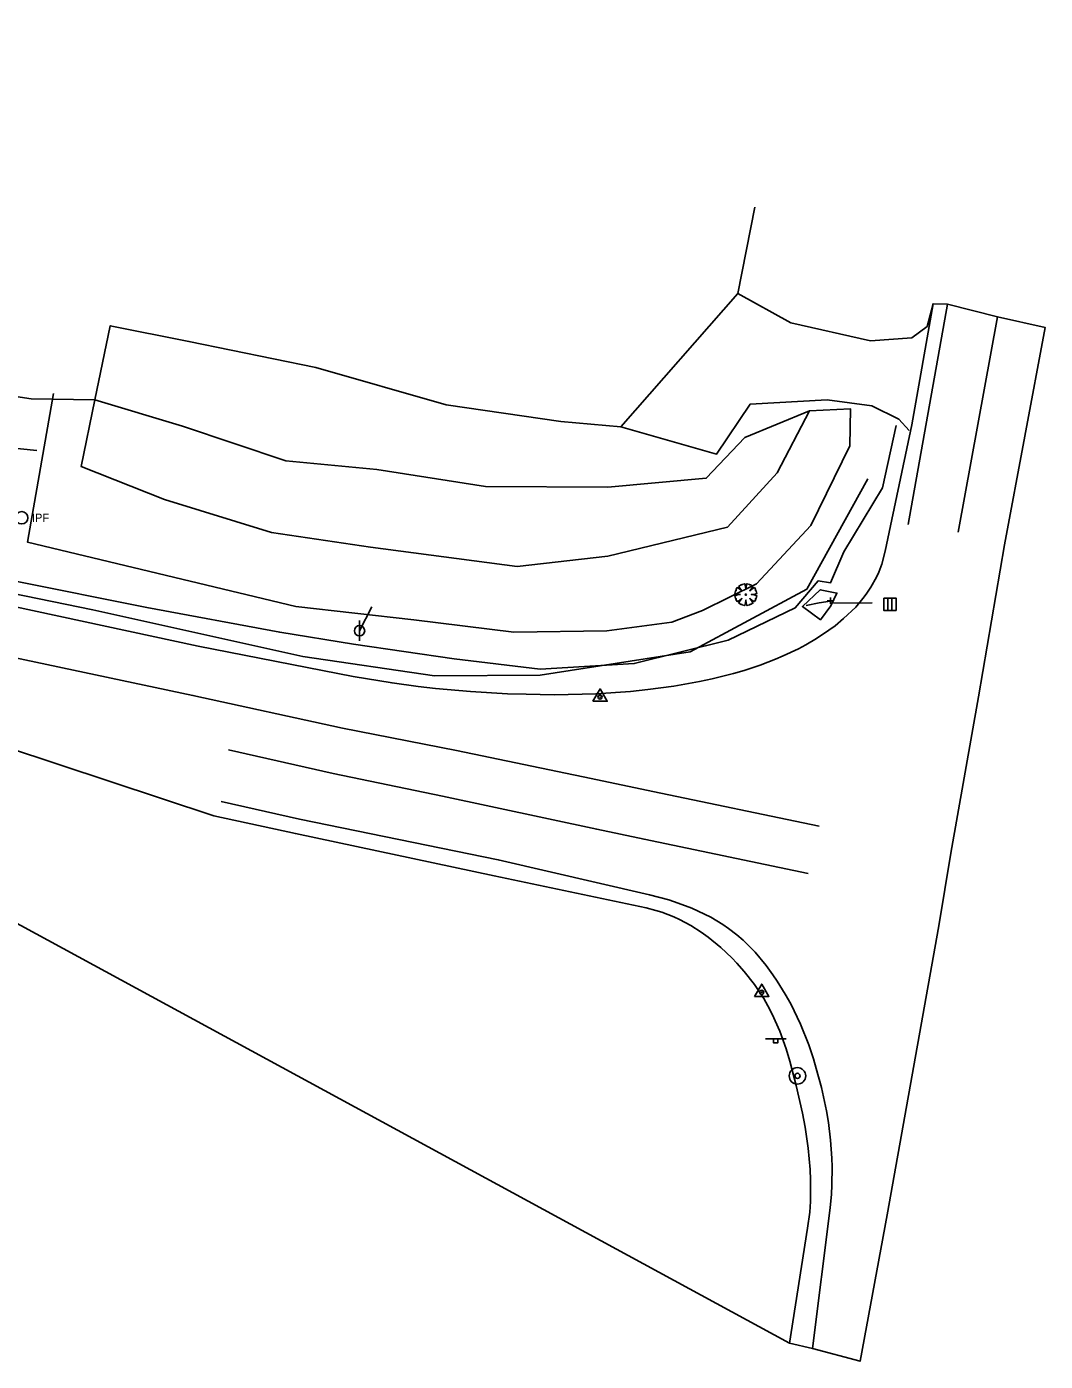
# Model space of a CAD drawing. Extents: x 1158469 to 1165378, y 609843 to 611748.
# Drawn here: x 1165130.6 to 1165377.8, y 609925.3 to 610249.2 of the extents above; entities that cross this region are included whole.
import ezdxf

# ---------------------------------------------------------------- set-up
doc = ezdxf.new("R2010")
doc.units = 0
for name, color, linetype in [('Exterior Boundary', 7, 'Continuous'), ('S_Control_Temp_Traverse', 7, 'Continuous'), ('S_Drainage_CB', 7, 'Continuous'), ('S_Drainage_Culvert_Top', 7, 'Continuous'), ('S_Drainage_Invert', 7, 'Continuous'), ('S_Drainage_RipRap', 7, 'Continuous'), ('S_Ground_Elevation', 7, 'Continuous'), ('S_Property_IronPipeFound', 7, 'Continuous'), ('S_Roadway_Centerline', 7, 'Continuous'), ('S_Roadway_Drive_Gravel', 7, 'Continuous'), ('S_Roadway_Edge_Pavement', 7, 'Continuous'), ('S_Roadway_Edge_TW', 7, 'Continuous'), ('S_Traffic_Sign_SinglePost', 7, 'Continuous'), ('S_Trees_Decid_NonPay', 7, 'Continuous'), ('S_Trees_HedgeLine', 7, 'Continuous'), ('S_Utilities_GuyWire3', 7, 'Continuous'), ('S_Utilities_Pole_Power', 7, 'Continuous'), ('S_Utilities_UG_Gas_Line', 7, 'Continuous'), ('S_Utilities_UG_Sanitary_MH', 7, 'Continuous')]:
    doc.layers.add(name, color=color, linetype=linetype)

msp = doc.modelspace()

# ---------------------------------------------------------------- linework, layer by layer
at = {"layer": 'Exterior Boundary'}
msp.add_lwpolyline([(1165125.5, 610033.08), (1165315.71, 609929.68), (1165321.34, 609928.43), (1165332.86, 609925.3), (1165339.45, 609960.81), (1165351.95, 610030.98), (1165354.88, 610048.57), (1165361.58, 610086.51), (1165367.96, 610123.43), (1165377.83, 610176.14), (1165366.26, 610178.75), (1165354.1, 610181.8), (1165350.58, 610181.93), (1165349.16, 610176.44), (1165345.45, 610173.65), (1165335.4, 610172.96), (1165316.03, 610177.29), (1165303.21, 610184.39), (1165274.79, 610152.06), (1165260.28, 610153.36), (1165232.4, 610157.43), (1165200.79, 610166.46), (1165170, 610172.78), (1165150.91, 610176.58), (1165147.13, 610158.61), (1165131.67, 610158.89), (1165111.05, 610162.04)], dxfattribs=at)
at = {"layer": 'S_Control_Temp_Traverse'}
for p, q in [((1165269.64, 610086.48), (1165269.89, 610086.48)), ((1165269.77, 610086.6), (1165269.77, 610086.35)), ((1165309, 610014.97), (1165309, 610014.72)), ((1165308.88, 610014.84), (1165309.13, 610014.84))]:
    msp.add_line(p, q, dxfattribs=at)
for points in [[(1165268.04, 610085.48), (1165271.5, 610085.48), (1165269.77, 610088.48)], [(1165307.27, 610013.84), (1165310.74, 610013.84), (1165309, 610016.84)]]:
    msp.add_lwpolyline(points, close=True, dxfattribs=at)
for centre in [(1165269.77, 610086.48), (1165309, 610014.84)]:
    msp.add_circle(centre, 0.5, dxfattribs=at)
at = {"layer": 'S_Drainage_CB'}
for p, q in [((1165339.6, 610110.52), (1165339.6, 610107.52)), ((1165340.6, 610110.52), (1165340.6, 610107.52))]:
    msp.add_line(p, q, dxfattribs=at)
msp.add_lwpolyline([(1165338.6, 610110.52), (1165341.6, 610110.52), (1165341.6, 610107.52), (1165338.6, 610107.52)], close=True, dxfattribs=at)
at = {"layer": 'S_Drainage_Culvert_Top'}
msp.add_lwpolyline([(1165326.39, 610109.26), (1165335.8, 610109.34)], dxfattribs=at)
at = {"layer": 'S_Drainage_Invert'}
for p, q in [((1165324.92, 610109.86), (1165326.42, 610109.86)), ((1165325.67, 610110.61), (1165325.67, 610109.11))]:
    msp.add_line(p, q, dxfattribs=at)
at = {"layer": 'S_Drainage_RipRap'}
msp.add_lwpolyline([(1165325.78, 610108.62), (1165323.24, 610105.26), (1165318.87, 610108.43), (1165323.22, 610112.52), (1165327.26, 610111.7)], close=True, dxfattribs=at)
at = {"layer": 'S_Ground_Elevation'}
for points in [[(1165131.67, 610158.89), (1165111.05, 610162.04), (1165081.66, 610169.51), (1165046.46, 610179.72), (1165010.53, 610187.31), (1164975.93, 610194.85), (1164954.17, 610199.11), (1164924.19, 610204.21), (1164911.82, 610196.02), (1164928.99, 610192.61), (1164954.02, 610185.41), (1164976.94, 610180.26), (1165003.93, 610175.22), (1165028.37, 610169.19), (1165050.08, 610165.24), (1165073.84, 610159.31), (1165096.89, 610152.98), (1165122.71, 610147.36), (1165133.09, 610146.34)], [(1165330.51, 610156.45), (1165320.59, 610155.91), (1165312.72, 610140.9), (1165300.67, 610127.75), (1165271.63, 610120.65), (1165249.68, 610118.14), (1165214.07, 610122.86), (1165190.07, 610126.42), (1165164.09, 610134.42), (1165143.88, 610142.41), (1165147.13, 610158.61), (1165150.91, 610176.58), (1165170, 610172.78), (1165200.79, 610166.46), (1165232.4, 610157.43), (1165260.28, 610153.36), (1165274.79, 610152.06)], [(1165130.83, 610124.06), (1165195.95, 610108.47), (1165224.59, 610105.19), (1165248.83, 610102.25), (1165271.38, 610102.55), (1165287.19, 610104.66), (1165294.61, 610107.47), (1165307.71, 610113.99), (1165320.93, 610128.15), (1165330.41, 610147.42), (1165330.51, 610156.45), (1165320.59, 610155.91), (1165304.87, 610149.46), (1165295.54, 610139.58), (1165271.68, 610137.46), (1165241.99, 610137.61), (1165215.59, 610141.67), (1165193.55, 610143.78), (1165168.4, 610152.23), (1165147.13, 610158.61)], [(1165341.63, 610152.38), (1165338.28, 610137.27), (1165328.96, 610121.76), (1165325.7, 610114.21), (1165322.7, 610114.67), (1165317.16, 610108.11), (1165300.9, 610100.28), (1165278.07, 610094.59), (1165255.25, 610093.27), (1165234.36, 610095.8), (1165209.94, 610099.32), (1165192.02, 610102.23), (1165159.8, 610108.25), (1165127.49, 610114.72)], [(1165325.61, 610109.73), (1165322.96, 610109.38), (1165319.8, 610108.74)]]:
    msp.add_lwpolyline(points, dxfattribs=at)
at = {"layer": 'S_Property_IronPipeFound'}
msp.add_circle((1165129.41, 610130), 1.5, dxfattribs=at)
at = {"layer": 'S_Roadway_Centerline'}
for points in [[(1165322.92, 610055.12), (1165282.59, 610063.58), (1165267.59, 610066.74), (1165234.97, 610073.48), (1165207.29, 610078.95), (1165170.95, 610086.9), (1165118.3, 610098.03), (1165065.91, 610108.93), (1165025.19, 610117.35), (1164995.59, 610123.89), (1164956.04, 610131.83), (1164919.32, 610140.12), (1164874.11, 610149.34), (1164822.77, 610160.96), (1164779.77, 610169.22), (1164696.7, 610187.78), (1164657.25, 610196.14), (1164616.44, 610205.3), (1164588.01, 610211.13), (1164540.84, 610220.89), (1164515.97, 610226.08), (1164470.96, 610235.38), (1164428.02, 610243.9), (1164400.81, 610249.16)], [(1165377.83, 610176.14), (1165367.96, 610123.43), (1165361.58, 610086.51), (1165354.88, 610048.57)], [(1165332.86, 609925.3), (1165339.45, 609960.81), (1165351.95, 610030.98)]]:
    msp.add_lwpolyline(points, dxfattribs=at)
at = {"layer": 'S_Roadway_Drive_Gravel'}
for points in [[(1165349.16, 610176.44), (1165345.45, 610173.65), (1165335.4, 610172.96), (1165316.03, 610177.29), (1165303.21, 610184.39), (1165307.34, 610205.39)], [(1165274.79, 610152.06), (1165297.99, 610145.41), (1165306.18, 610157.53), (1165324.85, 610158.65), (1165335.71, 610157.12), (1165342.28, 610153.92), (1165344.82, 610151.15)]]:
    msp.add_lwpolyline(points, dxfattribs=at)
at = {"layer": 'S_Roadway_Edge_Pavement'}
for points in [[(1165350.58, 610181.93), (1165345.47, 610152.58), (1165340.28, 610128.03), (1165339, 610121.88), (1165338.16, 610118.76), (1165337.41, 610116.8), (1165336.83, 610115.55), (1165335.51, 610113.16), (1165334.38, 610111.47), (1165333.57, 610110.39), (1165331.81, 610108.33), (1165328.89, 610105.51), (1165326.79, 610103.79), (1165325.33, 610102.71), (1165322.32, 610100.71), (1165319.68, 610099.17), (1165317.89, 610098.21), (1165314.23, 610096.46), (1165312.38, 610095.67), (1165308.6, 610094.23), (1165304.77, 610092.97), (1165302.19, 610092.22), (1165296.96, 610090.92), (1165293.87, 610090.25), (1165287.65, 610089.15), (1165281.39, 610088.3), (1165277.19, 610087.87), (1165268.78, 610087.3), (1165265.4, 610087.17), (1165258.62, 610087.06), (1165251.84, 610087.15), (1165247.33, 610087.3), (1165238.31, 610087.83), (1165229.85, 610088.58), (1165225.63, 610089.05), (1165219.3, 610089.9), (1165209.85, 610091.51), (1165172.21, 610098.85), (1165121.41, 610109.77)], [(1165315.71, 609929.68), (1165320.15, 609957.57), (1165320.64, 609961.5), (1165320.82, 609964.11), (1165320.88, 609969.3), (1165320.77, 609971.88), (1165320.3, 609977.01), (1165319.54, 609982.11), (1165318.9, 609985.5), (1165317.38, 609992.24), (1165315.81, 609998.16), (1165314.92, 610001.09), (1165313.38, 610005.39), (1165311.54, 610009.56), (1165310.5, 610011.58), (1165309.49, 610013.33), (1165307.26, 610016.7), (1165304.77, 610019.9), (1165302.98, 610021.92), (1165301.73, 610023.22), (1165299.11, 610025.69), (1165295.98, 610028.26), (1165294.34, 610029.45), (1165291.78, 610031.08), (1165289.09, 610032.52), (1165287.7, 610033.16), (1165284.8, 610034.27), (1165283.3, 610034.73), (1165280.97, 610035.31), (1165244.04, 610043.12), (1165195.85, 610053.35), (1165176.01, 610057.63), (1165125.74, 610074.35)]]:
    msp.add_lwpolyline(points, dxfattribs=at)
at = {"layer": 'S_Roadway_Edge_TW'}
for points in [[(1165354.1, 610181.8), (1165344.55, 610128.37)], [(1165366.26, 610178.75), (1165356.7, 610126.46)], [(1165320.28, 610043.71), (1165280.46, 610051.98), (1165268.97, 610054.42), (1165231.54, 610062.41), (1165205.02, 610067.95), (1165179.6, 610073.67)], [(1165321.34, 609928.43), (1165325.58, 609962.51), (1165325.92, 609965.85), (1165326.05, 609968.06), (1165326.11, 609972.45), (1165326.04, 609974.63), (1165325.72, 609978.96), (1165325.17, 609983.26), (1165324.69, 609986.1), (1165323.48, 609991.75), (1165322.25, 609996.38), (1165321.56, 609998.68), (1165320.4, 610002.09), (1165318.4, 610007.12), (1165316.05, 610012.02), (1165314.73, 610014.4), (1165312.78, 610017.58), (1165311.73, 610019.12), (1165310.07, 610021.37), (1165307.39, 610024.56), (1165304.48, 610027.47), (1165302.94, 610028.8), (1165300.93, 610030.35), (1165299.54, 610031.31), (1165296.65, 610033.05), (1165295.14, 610033.84), (1165292.02, 610035.27), (1165288.74, 610036.51), (1165286.48, 610037.25), (1165281.74, 610038.5), (1165245.05, 610047), (1165196.87, 610056.84), (1165177.78, 610061.12)]]:
    msp.add_lwpolyline(points, dxfattribs=at)
at = {"layer": 'S_Traffic_Sign_SinglePost'}
msp.add_line((1165309.9, 610003.55), (1165314.9, 610003.55), dxfattribs=at)
msp.add_lwpolyline([(1165311.9, 610003.55), (1165312.9, 610003.55), (1165312.9, 610002.55), (1165311.9, 610002.55)], close=True, dxfattribs=at)
at = {"layer": 'S_Trees_Decid_NonPay'}
msp.add_lwpolyline([(1165303.82, 610111.34), (1165303.13, 610111.39), (1165302.5, 610111.6), (1165302.65, 610112.29), (1165302.81, 610112.29), (1165302.76, 610112.51), (1165303.08, 610113.04), (1165303.61, 610112.77), (1165304.2, 610112.29), (1165303.72, 610112.88), (1165303.45, 610113.41), (1165303.98, 610113.73), (1165304.2, 610113.68), (1165304.2, 610113.84), (1165304.89, 610113.99), (1165305.1, 610113.36), (1165305.15, 610112.67), (1165305.21, 610113.36), (1165305.42, 610113.99), (1165306.11, 610113.84), (1165306.11, 610113.68), (1165306.32, 610113.73), (1165306.85, 610113.41), (1165306.59, 610112.88), (1165306.11, 610112.29), (1165306.69, 610112.77), (1165307.23, 610113.04), (1165307.54, 610112.51), (1165307.49, 610112.29), (1165307.65, 610112.29), (1165307.81, 610111.6), (1165307.17, 610111.39), (1165306.48, 610111.34), (1165307.17, 610111.28), (1165307.81, 610111.07), (1165307.65, 610110.38), (1165307.49, 610110.38), (1165307.54, 610110.17), (1165307.23, 610109.64), (1165306.69, 610109.9), (1165306.11, 610110.38), (1165306.59, 610109.8), (1165306.85, 610109.26), (1165306.32, 610108.95), (1165306.11, 610109), (1165306.11, 610108.84), (1165305.42, 610108.68), (1165305.21, 610109.32), (1165305.15, 610110.01), (1165305.1, 610109.32), (1165304.89, 610108.68), (1165304.2, 610108.84), (1165304.2, 610109), (1165303.98, 610108.95), (1165303.45, 610109.26), (1165303.72, 610109.8), (1165304.2, 610110.38), (1165303.61, 610109.9), (1165303.08, 610109.64), (1165302.76, 610110.17), (1165302.81, 610110.38), (1165302.65, 610110.38), (1165302.5, 610111.07), (1165303.13, 610111.28), (1165303.82, 610111.34)], dxfattribs=at)
msp.add_circle((1165305.15, 610111.34), 0.167, dxfattribs=at)
at = {"layer": 'S_Trees_HedgeLine'}
msp.add_lwpolyline([(1165137.15, 610160.11), (1165130.83, 610124.06), (1165195.95, 610108.47), (1165224.59, 610105.19), (1165248.83, 610102.25), (1165271.38, 610102.55), (1165287.19, 610104.66), (1165294.61, 610107.47)], dxfattribs=at)
at = {"layer": 'S_Utilities_GuyWire3'}
msp.add_lwpolyline([(1165211.4, 610102.59), (1165214.41, 610108.41)], dxfattribs=at)
at = {"layer": 'S_Utilities_Pole_Power'}
msp.add_line((1165211.4, 610105.09), (1165211.4, 610100.09), dxfattribs=at)
msp.add_circle((1165211.4, 610102.59), 1.25, dxfattribs=at)
at = {"layer": 'S_Utilities_UG_Gas_Line'}
msp.add_lwpolyline([(1164992.54, 610139.89), (1165045.26, 610128.69), (1165097.28, 610117.79), (1165146.7, 610107.65), (1165197.61, 610096.36), (1165229.6, 610091.61), (1165255.24, 610091.77), (1165291.62, 610097.45), (1165319.94, 610112.7), (1165334.73, 610139.41)], dxfattribs=at)
at = {"layer": 'S_Utilities_UG_Sanitary_MH'}
for radius in [2, 0.625]:
    msp.add_circle((1165317.67, 609994.56), radius, dxfattribs=at)

# ---------------------------------------------------------------- texts
at = {"layer": 'S_Property_IronPipeFound'}
msp.add_text('IPF', height=2, dxfattribs=at).set_placement((1165131.91, 610129))

doc.saveas('drawing.dxf')
